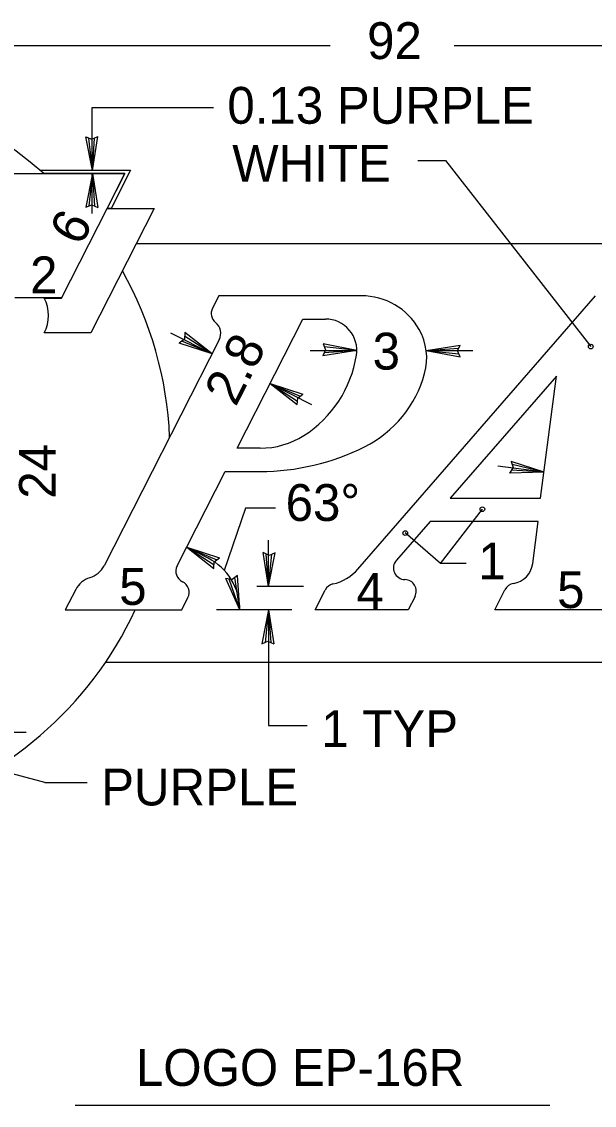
# Model space of a CAD drawing. Extents: x 10268197 to 10268739, y 2141503 to 2142677.
# Drawn here: x 10268620.18 to 10268632.91, y 2142399.34 to 2142423.43 of the extents above; entities that cross this region are included whole.
import ezdxf

# ---------------------------------------------------------------- set-up
doc = ezdxf.new("R2010")
doc.units = 0
for name, color, linetype in [('1', 7, 'Continuous'), ('21', 7, 'Continuous'), ('Default', 7, 'Continuous')]:
    doc.layers.add(name, color=color, linetype=linetype)

msp = doc.modelspace()

# ---------------------------------------------------------------- linework, layer by layer
at = {"layer": '1'}
for p, q in [((10268599.897, 2142422.903), (10268627.032, 2142422.903)), ((10268629.787, 2142422.903), (10268652.242, 2142422.903)), ((10268621.744, 2142421.526), (10268624.443, 2142421.526)), ((10268621.744, 2142420.156), (10268621.744, 2142421.526)), ((10268628.983, 2142420.348), (10268629.599, 2142420.348)), ((10268629.599, 2142420.348), (10268632.827, 2142416.209)), ((10268621.744, 2142419.171), (10268621.744, 2142420.063)), ((10268621.06, 2142417.287), (10268622.076, 2142419.281)), ((10268623.121, 2142419.281), (10268621.711, 2142416.514)), ((10268622.076, 2142419.281), (10268623.121, 2142419.281)), ((10268620.675, 2142417.287), (10268621.06, 2142417.287)), ((10268621.711, 2142416.514), (10268620.676, 2142416.514)), ((10268623.485, 2142416.517), (10268624.407, 2142416.047)), ((10268626.591, 2142416.124), (10268627.626, 2142416.124)), ((10268629.167, 2142416.124), (10268630.202, 2142416.124)), ((10268625.699, 2142415.39), (10268626.621, 2142414.92)), ((10268631.787, 2142413.416), (10268630.762, 2142413.551)), ((10268625.149, 2142412.618), (10268624.68, 2142411.233)), ((10268625.815, 2142412.618), (10268625.149, 2142412.618)), ((10268629.485, 2142411.388), (10268630.417, 2142412.595)), ((10268625.662, 2142410.872), (10268625.662, 2142411.906)), ((10268629.485, 2142411.388), (10268628.702, 2142412.065)), ((10268624.319, 2142411.507), (10268623.843, 2142411.75)), ((10268630.056, 2142411.388), (10268629.485, 2142411.388)), ((10268626.438, 2142410.872), (10268625.403, 2142410.872)), ((10268626.179, 2142410.354), (10268624.508, 2142410.354)), ((10268625.662, 2142410.354), (10268625.662, 2142407.783)), ((10268625.662, 2142407.783), (10268626.523, 2142407.783)), ((10268618.214, 2142407.638), (10268620.273, 2142407.638)), ((10268620.693, 2142406.521), (10268618.036, 2142407.216)), ((10268620.693, 2142406.521), (10268621.63, 2142406.521))]:
    msp.add_line(p, q, dxfattribs=at)
for centre in [(10268632.827, 2142416.208), (10268630.416, 2142412.594), (10268628.702, 2142412.064)]:
    msp.add_circle(centre, 0.0517, dxfattribs=at)
for centre, radius, start, end in [((10268619.943, 2142416.899), 0.828, 332.2089, 27.9127), ((10268623.731, 2142410.354), 1.294, 0, 62.9941)]:
    msp.add_arc(centre, radius, start, end, dxfattribs=at)
at = {"layer": '21'}
msp.add_line((10268621.363, 2142399.342), (10268631.919, 2142399.342), dxfattribs=at)
at = {"layer": 'Default'}
for p, q in [((10268621.746, 2142420.12), (10268621.6, 2142420.872)), ((10268621.6, 2142420.872), (10268621.734, 2142420.817)), ((10268621.746, 2142420.12), (10268621.67, 2142420.843)), ((10268621.734, 2142420.817), (10268621.866, 2142420.876)), ((10268621.746, 2142420.12), (10268621.866, 2142420.876)), ((10268621.746, 2142420.12), (10268621.797, 2142420.844)), ((10268613.674, 2142420.056), (10268622.471, 2142420.056)), ((10268620.58, 2142420.134), (10268622.597, 2142420.134)), ((10268622.471, 2142420.056), (10268621.062, 2142417.29)), ((10268621.746, 2142420.058), (10268621.6, 2142419.306)), ((10268621.746, 2142420.058), (10268621.67, 2142419.335)), ((10268621.746, 2142420.058), (10268621.866, 2142419.302)), ((10268621.746, 2142420.058), (10268621.797, 2142419.334)), ((10268622.597, 2142420.134), (10268622.162, 2142419.281)), ((10268621.6, 2142419.306), (10268621.734, 2142419.362)), ((10268621.734, 2142419.362), (10268621.866, 2142419.302)), ((10268621.06, 2142417.287), (10268622.076, 2142419.281)), ((10268623.121, 2142419.281), (10268621.711, 2142416.514)), ((10268622.076, 2142419.281), (10268623.121, 2142419.281)), ((10268622.725, 2142418.504), (10268652.242, 2142418.504)), ((10268621.062, 2142417.29), (10268620.026, 2142417.29)), ((10268620.675, 2142417.287), (10268621.06, 2142417.287)), ((10268624.559, 2142417.34), (10268624.418, 2142417.064)), ((10268627.728, 2142417.34), (10268624.559, 2142417.34)), ((10268627.648, 2142411.263), (10268632.932, 2142417.34)), ((10268624.965, 2142413.951), (10268626.429, 2142416.822)), ((10268626.429, 2142416.822), (10268626.928, 2142416.822)), ((10268621.711, 2142416.514), (10268620.676, 2142416.514)), ((10268623.804, 2142416.519), (10268623.792, 2142416.374)), ((10268624.407, 2142416.047), (10268623.798, 2142416.443)), ((10268624.407, 2142416.047), (10268623.804, 2142416.519)), ((10268624.568, 2142416.362), (10268622.006, 2142411.334)), ((10268623.792, 2142416.374), (10268623.679, 2142416.284)), ((10268624.407, 2142416.047), (10268623.679, 2142416.284)), ((10268624.407, 2142416.047), (10268623.739, 2142416.331)), ((10268627.626, 2142416.124), (10268626.874, 2142416.27)), ((10268626.874, 2142416.27), (10268626.93, 2142416.136)), ((10268627.626, 2142416.124), (10268626.903, 2142416.2)), ((10268629.167, 2142416.124), (10268629.925, 2142416.244)), ((10268629.865, 2142416.112), (10268629.925, 2142416.244)), ((10268626.93, 2142416.136), (10268626.869, 2142416.004)), ((10268627.626, 2142416.124), (10268626.869, 2142416.004)), ((10268627.626, 2142416.124), (10268626.902, 2142416.073)), ((10268629.167, 2142416.124), (10268629.892, 2142416.175)), ((10268629.167, 2142416.124), (10268629.92, 2142415.978)), ((10268629.167, 2142416.124), (10268629.891, 2142416.048)), ((10268629.92, 2142415.978), (10268629.865, 2142416.112)), ((10268632.066, 2142415.555), (10268629.704, 2142412.838)), ((10268631.712, 2142412.838), (10268632.066, 2142415.555)), ((10268625.699, 2142415.39), (10268626.428, 2142415.154)), ((10268625.699, 2142415.39), (10268626.303, 2142414.918)), ((10268625.699, 2142415.39), (10268626.309, 2142414.995)), ((10268625.699, 2142415.39), (10268626.368, 2142415.107)), ((10268626.303, 2142414.918), (10268626.314, 2142415.063)), ((10268626.314, 2142415.063), (10268626.428, 2142415.154)), ((10268625.478, 2142413.951), (10268624.965, 2142413.951)), ((10268631.787, 2142413.416), (10268631.06, 2142413.658)), ((10268631.06, 2142413.658), (10268631.099, 2142413.518)), ((10268631.787, 2142413.416), (10268631.08, 2142413.585)), ((10268623.631, 2142411.334), (10268624.701, 2142413.433)), ((10268624.701, 2142413.433), (10268625.478, 2142413.433)), ((10268631.099, 2142413.518), (10268631.022, 2142413.395)), ((10268631.787, 2142413.416), (10268631.022, 2142413.395)), ((10268631.787, 2142413.416), (10268631.063, 2142413.459)), ((10268629.704, 2142412.838), (10268631.712, 2142412.838)), ((10268629.255, 2142412.32), (10268628.505, 2142411.459)), ((10268631.66, 2142412.32), (10268629.255, 2142412.32)), ((10268631.537, 2142411.385), (10268631.66, 2142412.32)), ((10268623.843, 2142411.75), (10268624.571, 2142411.512)), ((10268623.843, 2142411.75), (10268624.446, 2142411.278)), ((10268623.843, 2142411.75), (10268624.452, 2142411.354)), ((10268623.843, 2142411.75), (10268624.511, 2142411.465)), ((10268625.662, 2142410.872), (10268625.542, 2142411.628)), ((10268625.674, 2142411.568), (10268625.542, 2142411.628)), ((10268625.662, 2142410.872), (10268625.808, 2142411.624)), ((10268625.808, 2142411.624), (10268625.674, 2142411.568)), ((10268624.446, 2142411.278), (10268624.457, 2142411.422)), ((10268624.457, 2142411.422), (10268624.571, 2142411.512)), ((10268625.662, 2142410.872), (10268625.611, 2142411.596)), ((10268625.662, 2142410.872), (10268625.737, 2142411.595)), ((10268625.025, 2142410.354), (10268624.713, 2142411.055)), ((10268624.856, 2142411.031), (10268624.713, 2142411.055)), ((10268625.025, 2142410.354), (10268624.788, 2142411.041)), ((10268624.971, 2142411.119), (10268624.856, 2142411.031)), ((10268625.025, 2142410.354), (10268624.911, 2142411.072)), ((10268625.025, 2142410.354), (10268624.971, 2142411.119)), ((10268621.377, 2142410.811), (10268621.145, 2142410.354)), ((10268626.697, 2142410.354), (10268626.922, 2142410.797)), ((10268630.69, 2142410.354), (10268630.918, 2142410.804)), ((10268623.732, 2142410.354), (10268623.872, 2142410.631)), ((10268628.919, 2142410.653), (10268628.766, 2142410.354)), ((10268621.145, 2142410.354), (10268623.732, 2142410.354)), ((10268625.662, 2142410.354), (10268625.516, 2142409.602)), ((10268625.662, 2142410.354), (10268625.586, 2142409.632)), ((10268625.662, 2142410.354), (10268625.781, 2142409.598)), ((10268625.662, 2142410.354), (10268625.712, 2142409.63)), ((10268628.766, 2142410.354), (10268626.697, 2142410.354)), ((10268633.277, 2142410.354), (10268630.69, 2142410.354)), ((10268625.516, 2142409.602), (10268625.65, 2142409.658)), ((10268625.65, 2142409.658), (10268625.781, 2142409.598)), ((10268622.038, 2142409.19), (10268647.496, 2142409.19))]:
    msp.add_line(p, q, dxfattribs=at)
msp.add_lwpolyline([(10268620.58, 2142420.134), (10268622.597, 2142420.134), (10268622.162, 2142419.281), (10268622.076, 2142419.281), (10268622.471, 2142420.056), (10268620.669, 2142420.056)], close=True, dxfattribs=at)
for centre, radius, start, end in [((10268615.193, 2142413.846), 8.279, 48.5904, 217.4727), ((10268615.193, 2142413.846), 8.279, 2.4236, 29.2771), ((10268619.943, 2142416.899), 0.828, 332.2089, 27.9127), ((10268627.728, 2142415.864), 1.475, 29.4315, 90), ((10268624.648, 2142416.945), 0.259, 152.9784, 231.1602), ((10268624.291, 2142416.502), 0.31, 333.0027, 51.1602), ((10268626.927, 2142416.123), 0.699, 351.076, 90), ((10268627.885, 2142415.953), 1.294, 344.7074, 29.4315), ((10268625.061, 2142416.416), 2.587, 302.4206, 351.076), ((10268626.638, 2142416.294), 2.587, 296.6431, 344.7074), ((10268625.477, 2142415.761), 1.811, 270, 302.4206), ((10268625.477, 2142418.607), 5.174, 270, 296.6431), ((10268628.7, 2142411.288), 0.259, 138.9824, 268.6869), ((10268631.024, 2142411.452), 0.517, 279.2397, 352.5632), ((10268621.545, 2142411.568), 0.517, 286.4317, 332.9959), ((10268623.862, 2142411.216), 0.259, 152.9884, 244.7832), ((10268626.868, 2142411.941), 1.035, 282.7162, 318.9966), ((10268621.838, 2142410.575), 0.517, 106.4317, 152.9742), ((10268623.641, 2142410.748), 0.259, 333.0239, 64.7832), ((10268627.152, 2142410.679), 0.259, 102.7162, 153.0239), ((10268628.688, 2142410.77), 0.259, 332.9784, 88.6869), ((10268631.149, 2142410.685), 0.259, 99.2397, 153.0239), ((10268615.193, 2142413.846), 8.279, 237.5383, 335.047)]:
    msp.add_arc(centre, radius, start, end, dxfattribs=at)

# ---------------------------------------------------------------- texts
at = {"layer": '1'}
for s, height, p in [('92', 0.8187, (10268627.854, 2142422.601)), ('0.13 PURPLE', 0.81867, (10268624.747, 2142421.163)), ('WHITE', 0.8187, (10268624.855, 2142419.875)), ('2', 0.819, (10268620.362, 2142417.393)), ('3', 0.819, (10268627.977, 2142415.698)), ('63°', 0.8187, (10268626.043, 2142412.333)), ('1', 0.819, (10268630.327, 2142411.032)), ('5', 0.819, (10268622.343, 2142410.467)), ('4', 0.819, (10268627.616, 2142410.36)), ('5', 0.819, (10268632.078, 2142410.397)), ('1 TYP', 0.8187, (10268626.834, 2142407.307)), ('PURPLE', 0.8187, (10268621.942, 2142406.009)), ('LOGO EP-16R', 0.81867, (10268622.714, 2142399.774))]:
    msp.add_text(s, height=height, dxfattribs=at).set_placement(p)
for s, height, rotation, p in [('6', 0.819, 63, (10268621.492, 2142418.417)), ('2.8', 0.8187, 62.9907, (10268624.933, 2142414.853)), ('24', 0.8187, 90, (10268620.934, 2142412.827))]:
    msp.add_text(s, height=height, rotation=rotation, dxfattribs=at).set_placement(p)

doc.saveas('drawing.dxf')
